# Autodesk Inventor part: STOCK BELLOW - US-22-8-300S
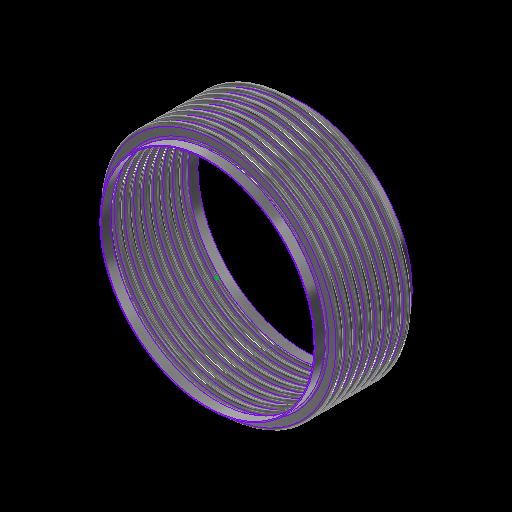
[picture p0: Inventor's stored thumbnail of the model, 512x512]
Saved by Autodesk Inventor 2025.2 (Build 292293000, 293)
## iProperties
Category: 16 GA (0.060 THICK)
RuleStatus: InUse
Created: 2024-01
Part Number: STOCK BELLOW - US-22-8-300S
Project: =STOCK BELLOWS: <Stock Number><SFILL>
Material: ASTM A240-304
Description: =STOCK BELLOWS: <Stock Number>, <SID_> I.D., <SOD_> O.D., <SPLY_> PLY, <Category>, <SNET_CONS> CONS.<PITCH_><STANGENT_> TANGENT<SFILL>
Document SubType Name: Sheet Metal
Designer: GS
Stock Number: U.S-22-8-300S
Surface Area: 25469.6 cm^2
Volume: 3832.38 cm^3
Sheet Metal Rule: Default
Appearance: STAINLESS STEEL
Mass: 30878.6 g
Density: 8.05729 g/cm^3
THK: 0.036
ID: 3.500
OD: 4.250
CONS_: 2
PITCH: 0.500
TANGENT: 0.500
BELLOWS_UPSET: 0.000
d79: 1.000
d82: 1.000
d83: 26.000
d84: 24.000
d174: 8
d214: 8
STHK_: 0.060
SID_: 22.000
SOD_: 24.750
SPITCH_: 1.000
STANGENT__: 1.000
SBELLOWS_UPSET_: 0.000
SDIFF_TAN: 1.000
d252: 2
d275: 2
d287: 0.050
d289: 0.500
d290: 0.000
SOD_NECK: 22 1/4
PLY: 1
PSET: 4.178
PBAR: 1.035
COUNTER: 1.500
NET_TUBE: 3.071
CONS: 2
S_CONS: 0
NET_CONS: 2
ID_M: 88.90 mm
OD_M: 107.95 mm
THK_M: 0.91 mm
ID_U: 3.500 in
OD_U: 4.250 in
THK_U: 0.036 in
TANGENT2: 0.500
TAN_TO_TAN: 1.000 in
d80: 2.571
d81: 10
SID: 2.375
SCONS_: 8
SPITCH: 0.250
STANGENT_: 1.000
SBELLOWS_UPSET: 0.000
SNET_CONS: 8
SS_CONS: 0
SCONS: 8
d190: 8
d191: 1
d192: 1
d193: 8
d194: 0
SIZE: 22.00
PRESSURE: 300
d230: 8
STANGENT: 4.000
SPLY_: 2
d233: 8
d234: 0
d263: 2
d265: 1
d268: 2
d269: 0
d286: 2
d288: 1
d291: 2
d292: 0
SREROLL: 0.750
BLETP: 0.000 ul
PRES_Copy: 85
MATTABLE: 20 GA (0.036 THICK)
PART_NUMBER: U.S-22-8-300S
PITCH_: =, <SPITCH_> PITCH,
CFILL: .
SFILL: .
MESH: ,
COMP: 1.4
EXT: 0.70
LAT: 0.16
ANG: 344
ASR: 9507
LSR: 121742
ANSR: 17434
PRES: 300
COMPM: 14.0
EXTM: 7.0
LATM: 1.60
ASRM: 1664.961
PRESM: 20.684
LSRM: 21320.676
ANSRM: 3053.216
TEMPMIN: 20
TEMPMAX: 800
TEMPMINM: -7
TEMPMAXM: 427
WEIGHTM: 30.879
WEIGHT: 68.076
Author: GS
Keywords: 20 GA (0.036 THICK)
Comments: =STOCK BELLOW - <STOCK NUMBER>
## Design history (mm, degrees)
sketch "Sketch2"
  geometry: L1 (0, -177.245)-(0, 562.856) reference; L2 (45.364, 0)-(44.45, 0); L3 (48.082, -2.718)-(50.343, -2.718); L4 (48.082, -3.632)-(50.343, -3.632); L5 (50.343, -9.982)-(48.082, -9.982); L6 (50.343, -9.068)-(48.082, -9.068); L7 (45.364, -12.7)-(44.45, -12.7); L8 (48.082, 0)-(48.082, -12.7); L9 (50.343, -6.35)-(53.975, -6.35); L10 (44.45, 0)-(44.45, -12.7); L11 (20.376, 102.841)-(20.376, 101.926); L12 (58.262, 457.127)-(58.262, 349.177); L13 (58.262, 444.427)-(58.262, 336.477); L14 (93.133, -58.817)-(93.133, -71.517); L15 (118.746, -66.401)-(118.746, -66.401); L16 (50.343, -9.068)-(50.343, -9.982); L17 (48.082, -9.068)-(48.082, -9.982); L18 (48.082, -9.525)-(50.343, -9.525); L19 (53.975, 0)-(53.975, -12.7); L20 (-50.343, -9.068)-(-50.343, -9.982); L21 (-50.343, -2.718)-(-48.082, -2.718); L22 (-50.343, -3.632)-(-48.082, -3.632); L23 (-48.082, -9.068)-(-50.343, -9.068); L24 (-50.343, -9.525)-(-48.082, -9.525); L25 (-48.082, -9.982)-(-50.343, -9.982); L26 (-48.082, -9.068)-(-48.082, -9.982); L27 (-44.45, 0.653)-(-44.45, -12.047); L28 (-48.082, -6.35)-(-44.45, -6.35); L29 (-50.343, 0.653)-(-50.343, -12.7); L30 (-53.061, 0)-(-53.975, 0); L31 (-53.975, 0)-(-53.975, -12.7); L32 (-53.061, -12.7)-(-53.975, -12.7); A1 r 2.718 centre (48.082, 0) between (45.364, 0) and (48.082, -2.718); A2 r 3.632 centre (48.082, 0) between (44.45, 0) and (48.082, -3.632); A3 r 3.632 centre (50.343, -6.35) between (50.343, -9.982) and (50.343, -2.718); A4 r 2.718 centre (50.343, -6.35) between (50.343, -9.068) and (50.343, -3.632); A5 r 2.718 centre (48.082, -12.7) between (48.082, -9.982) and (45.364, -12.7); A6 r 3.632 centre (48.082, -12.7) between (48.082, -9.068) and (44.45, -12.7); A7 r 3.175 centre (50.343, -6.35) between (50.343, -9.525) and (53.518, -6.35); A8 r 3.175 centre (48.082, -12.7) between (48.082, -9.525) and (44.907, -12.7); A9 r 2.718 centre (-50.343, -12.7) between (-50.343, -9.982) and (-53.061, -12.7); A10 r 2.718 centre (-48.082, -6.35) between (-48.082, -9.068) and (-48.082, -3.632); A11 r 3.175 centre (-48.082, -6.35) between (-48.082, -9.525) and (-44.907, -6.35); A12 r 3.632 centre (-48.082, -6.35) between (-48.082, -9.982) and (-48.082, -2.718); A13 r 3.175 centre (-50.343, -12.7) between (-50.343, -9.525) and (-53.518, -12.7); A14 r 3.632 centre (-50.343, -12.7) between (-50.343, -9.068) and (-53.975, -12.7); A15 r 2.718 centre (-50.343, 0) between (-53.061, 0) and (-50.343, -2.718); A16 r 3.632 centre (-50.343, 0) between (-53.975, 0) and (-50.343, -3.632); 10 further points
  constraints: 62 end point, 38 point on circle, 20 tangent, 16 centre point, 12 parallel, 9 midpoint, 7 vertical, 6 coincident, 6 concentric, 6 point on line, 4 equal radius, 4 perpendicular, 3 horizontal, 1 collinear, 1 horizontal alignment, 10 other
  dimensions: "THK" = 0.9144 distance of L11.start L11.end; "ID" = 88.9 distance of L11.end point (20.376, 13.026); "OD" = 107.95 distance of L12.start L12.end; "PITCH" = 12.7 distance of L12.start L13.start; "TANGENT" = 12.7 distance of L14.start L14.end; "BELLOWS_UPSET" = 0 distance of L15.start L15.end; "d43" = 88.9 diameter of L10 L1 (= ID); "d44" = 107.95 diameter of L9.end L1 (= OD); "d45" = 0.9144 distance between parallel lines of L5 L6 (computed from THK, PLY); "d46" = 3.6322 radius of A3 (computed from PITCH, THK, PLY); "UPSET_PITCH" = 12.7 distance of L2.end L7.end (derived); "SIDEWALL_ANGLE" = 360 deg dimension on L3 L9 (derived); "CON_GAP" = 5.4356 distance of point (48.082, -9.068) point (48.082, -3.632) (derived); "TAN1" = 4.98728 dimension on A8 (derived); "TAN2" = 4.98728 dimension on A7 (derived); "LEG1" = 2.2606 distance of L18.start L18.end (derived); "d278" = 0.9144 distance between parallel lines of L25 L23 (derived); "d279" = 3.6322 radius of A12 (derived); "d280" = 12.7 distance of L30.end L31.end (derived); "d281" = 360 deg dimension on L21 L28 (derived); "d282" = 5.4356 distance of point (-50.343, -9.068) point (-50.343, -3.632) (derived); "d283" = 4.98728 dimension on A13 (derived); "d284" = 4.98728 dimension on A11 (derived); "d285" = 2.2606 distance of L24.start L24.end (derived); "d293" = 88.9 diameter of L27 L1 (derived); "d294" = 107.95 diameter of L31 L1 (derived)
  node "Sketch Rectangular Pattern1" dims "d31" = 25.4, "ID" = 88.9
  node "Sketch Rectangular Pattern2" dims "d39" = 25.4, "PITCH" = 12.7
revolve "CONS" stored, may be unused: angle "d48" = 90 deg
node "BELLOW MIDPLANE"
pattern_linear "Rectangular Pattern2" dims "d52" = 12.7 (= UPSET_PITCH)
sketch "Sketch5"
  geometry: C1 r 45.364 at (0, 0) reference; C2 r 44.45 at (0, 0) reference
extrude "TANGENT" new body sketch "Sketch5" distance "d53" = 12.7 (= TANGENT); taper "d54" = 0 deg
revolve "SAMETAN" stored, may be unused: angle "d65" = 90 deg
revolve "DIFFTAN" stored, may be unused: angle "d70" = 90 deg
sketch "Sketch9"
  geometry: L1 (53.319, 0)-(-53.319, 0) reference; L2 (0, -17.78)-(0, 17.78) reference; L3 (38.085, 0)-(-38.085, 0); L4 (38.085, -11.906)-(38.085, 11.906); L5 (25.385, -11.906)-(25.385, 11.906); L6 (13.15, 11.906)-(13.15, -11.906); L7 (-25.385, -11.906)-(-25.385, 11.906); L8 (-38.085, -11.906)-(-38.085, 11.906); L9 (37.291, -11.906)-(37.291, 11.906); L10 (38.085, -11.906)-(37.291, -11.906); L11 (38.085, 11.906)-(37.291, 11.906); L12 (13.546, 11.906)-(12.753, 11.906); L13 (12.753, 11.906)-(12.753, -11.906); L14 (12.753, -11.906)-(13.546, -11.906); L15 (13.546, -11.906)-(13.546, 11.906); L16 (-13.546, 11.906)-(-13.546, -11.906); L17 (-13.15, 11.906)-(-13.15, -11.906); L18 (-13.546, -11.906)-(-12.753, -11.906); L19 (-12.753, -11.906)-(-12.753, 11.906); L20 (-12.753, 11.906)-(-13.546, 11.906); L21 (-38.085, -11.906)-(-37.291, -11.906); L22 (-37.291, -11.906)-(-37.291, 11.906); L23 (-37.291, 11.906)-(-38.085, 11.906); L24 (-38.085, 11.906)-(-38.085, -11.906); L25 (38.085, -0.397)-(-38.085, -0.397); L26 (-38.085, -0.397)-(-38.085, 0.397); L27 (-38.085, 0.397)-(38.085, 0.397); L28 (38.085, 0.397)-(38.085, -0.397); L29 (-38.085, 11.906)-(38.085, 11.906); L30 (38.085, 11.906)-(38.085, 12.7); L31 (38.085, 12.7)-(-38.085, 12.7); L32 (-38.085, 12.7)-(-38.085, 11.906); L33 (38.085, -11.906)-(-38.085, -11.906); L34 (-38.085, -11.906)-(-38.085, -12.7); L35 (-38.085, -12.7)-(38.085, -12.7); L36 (38.085, -12.7)-(38.085, -11.906); 30 further points
  constraints: 68 end point, 13 midpoint, 13 parallel, 8 horizontal, 7 perpendicular, 6 equal length, 3 point on line, 2 vertical, 14 other
  dimensions: "d115" = 23.8125 distance of L4.start L4.end (derived); "d116" = 12.7 distance between parallel lines of L4 L5 (derived); "d117" = 12.23516 distance between parallel lines of L5 L6 (derived); "d125" = 38.53427 distance between parallel lines of L7 L6 (derived); "d127" = 12.7 distance between parallel lines of L8 L7 (derived); "d128" = 24.93516 distance between parallel lines of L6 L4 (derived); "d130" = 76.16943 distance between parallel lines of L8 L4 (derived); "RULER_THK" = 0.79375 distance between parallel lines of L4 L9; "d135" = 0.79375 distance of L13.end L14.end (derived); "d138" = 26.29911 distance of L13.end L16.end (derived); "d143" = 0.79375 distance of L22.end L8.end (derived); "d144" = 0.79375 distance between parallel lines of L27 L25 (derived)
extrude "RULER" join sketch "Sketch9" distance "d149" = 0.79375 (derived); taper "d150" = 0 deg
extrude "BARS" join sketch "Sketch9" distance "d151" = 0.79375 (derived); taper "d152" = 0 deg
pattern_linear "Rectangular Pattern4" dims "d155" = 26.29911 (derived)
sketch "Sketch13"
  geometry: L1 (93.149, -52.467)-(93.149, -77.867); L2 (282.448, 0)-(279.4, 0); L3 (282.448, -25.4)-(279.4, -25.4); L4 (306.451, -20.574)-(287.274, -20.574); L5 (306.451, -17.526)-(287.274, -17.526); L6 (306.451, -12.7)-(314.325, -12.7); L7 (287.274, -4.826)-(306.451, -4.826); L8 (287.274, 0)-(287.274, -25.4); L9 (279.4, 0)-(279.4, -25.4); L10 (58.254, 132.219)-(58.254, -496.431); L11 (58.254, 106.819)-(58.254, -521.831); L12 (58.254, 56.019)-(58.254, -572.631); L13 (58.254, 30.619)-(58.254, -598.031); L14 (58.254, 5.219)-(58.254, -623.431); L15 (58.254, -20.181)-(58.254, -648.831); L16 (58.254, -45.581)-(58.254, -674.231); L17 (58.254, 81.419)-(58.254, -547.231); L18 (20.376, 103.45)-(20.376, 101.926); L19 (287.274, -7.874)-(306.451, -7.874); L20 (0, -835.521)-(0, 293.509) reference; L21 (-62.865, 0)-(377.19, 0) reference; A1 r 4.826 centre (287.274, 0) between (282.448, 0) and (287.274, -4.826); A2 r 4.826 centre (287.274, -25.4) between (287.274, -20.574) and (282.448, -25.4); A3 r 7.874 centre (287.274, -25.4) between (287.274, -17.526) and (279.4, -25.4); A4 r 4.826 centre (306.451, -12.7) between (306.451, -17.526) and (306.451, -7.874); A5 r 7.874 centre (306.451, -12.7) between (306.451, -20.574) and (306.451, -4.826); A6 r 7.874 centre (287.274, 0) between (279.4, 0) and (287.274, -7.874); 6 further points; 1 other entity
  constraints: 38 end point, 15 point on circle, 9 tangent, 6 centre point, 6 parallel, 5 vertical alignment, 4 point on line, 4 vertical, 3 coincident, 3 concentric, 2 collinear, 2 equal radius, 1 horizontal, 1 perpendicular, 23 other
  dimensions: "SBELLOWS_UPSET_" = 0 distance of point (118.762, -66.401) point (118.762, -66.401); "STOTAL_THK_BELLOW__" = 3.048 distance between parallel lines of L4 L5 (derived); "d224" = 7.874 radius of A5 (derived); "d225" = 25.4 distance of L2.end L3.end (derived); "SSIDEWALL_ANGLE_" = 360 deg dimension on L7 L6 (derived); "SSCON_GAP_" = 9.652 distance of point (287.274, -17.526) point (287.274, -7.874) (derived); "d235" = 558.8 diameter of L9 L20 (derived); "d236" = 628.65 diameter of L6.end L20 (derived)
  node "Sketch Rectangular Pattern4" dims "d228" = 25.4
  node "Sketch Rectangular Pattern5" dims "d229" = 25.4
revolve "SBELLOW" stored, may be unused: angle "d197" = 90 deg
pattern_linear "Rectangular Pattern5" dims "d204" = 25.4 (derived)
revolve "STANGENT" stored, may be unused: angle "d240" = 90 deg
revolve "SSAMETAN" stored, may be unused: angle "d241" = 90 deg
revolve "SDIFFTAN" stored, may be unused: angle "d246" = 90 deg
revolve "INVCON" stored, may be unused: angle "d295" = 90 deg
pattern_linear "Rectangular Pattern6" dims "d298" = 12.7 (derived)
revolve "INVTANGENT" stored, may be unused: angle "d302" = 90 deg
revolve "INVSAMETAN" stored, may be unused: angle "d307" = 90 deg
revolve "INVDIFFTAN" stored, may be unused: angle "d312" = 90 deg
sketch "ID BELLOW MOUNT CALC"
  geometry: L1 (44.45, 0)-(38.1, 0); L2 (38.1, 0)-(38.1, 12.7); L3 (38.1, 12.7)-(44.45, 12.7); L4 (44.45, 12.7)-(44.45, 0); L5 (36.513, 12.7)-(35.598, 12.7); L6 (35.598, 12.7)-(35.598, 0); L7 (35.598, 0)-(36.513, 0); L8 (36.513, 0)-(36.513, 12.7); L9 (0, -2.54)-(0, 15.24) reference; L10 (-8.89, 0)-(53.34, 0) reference; 1 further point
  constraints: 16 end point, 5 parallel, 2 collinear, 2 horizontal, 2 perpendicular
  dimensions: "d314" = 12.7 distance of L5.end L6.end (derived); "d315" = 0.9144 distance of L5.start L5.end (derived); "IG" = 1.5875 distance between parallel lines of L2 L8; "PIPE_OD" = 88.9 diameter of L4 L9; "PIPE_WALL" = 6.35 distance of L2.end L3.end; "ID_MT_BELLOW" = 71.1962 diameter of L6 L9 (derived)
revolve "CFILL" stored, may be unused: angle "d320" = 90 deg
pattern_linear "Rectangular Pattern7" dims "d323" = 12.7 (derived)
revolve "SFILL" stored, may be unused: angle "d324" = 90 deg
pattern_linear "Rectangular Pattern8" dims "d327" = 25.4 (derived)
node "STOCK BELLOW MIDPLANE"
node "BELLOW"
sketch "Sketch6"
  geometry: L1 (-12.7, 45.364)-(0, 45.364); L2 (0, 45.364)-(0, 44.45); L3 (0, 44.45)-(-12.7, 44.45); L4 (-12.7, 44.45)-(-12.7, 45.364); L5 (10.16, 0)-(-60.96, 0) reference; L6 (-38.1, -89.422)-(-38.1, 153.44) reference; 1 further point
  constraints: 8 end point, 2 parallel, 1 horizontal, 1 perpendicular
  dimensions: "d61" = 12.7 distance of L2.end L3.end (derived); "d62" = 0.9144 distance of L1.end L2.end (derived); "d63" = 88.9 diameter of L3 L5 (derived); "d64" = 25.4 distance between parallel lines of L4 L6 (derived)
sketch "Sketch12"
  geometry: 1 further point
sketch "Sketch14"
  geometry: L1 (-25.4, 282.448)-(0, 282.448); L2 (0, 282.448)-(0, 279.4); L3 (0, 279.4)-(-25.4, 279.4); L4 (-25.4, 279.4)-(-25.4, 282.448); L5 (5.08, 0)-(-30.48, 0) reference; L6 (0, -56.49)-(0, 338.938) reference; 1 further point
  constraints: 8 end point, 2 parallel, 1 collinear, 1 horizontal, 1 perpendicular
  dimensions: "d237" = 3.048 distance of L3.end L1.start (derived); "d238" = 558.8 diameter of L3 L5 (derived); "d239" = 25.4 distance of L1.start L1.end (derived); "SOD_NECK" = 564.896 diameter of L1 L5 (derived)
sketch "Sketch15"
  geometry: L1 (-56.49, 0)-(338.938, 0) reference; L2 (279.4, -203.2)-(282.448, -203.2); L3 (282.448, -203.2)-(282.448, -228.6); L4 (282.448, -228.6)-(279.4, -228.6); L5 (279.4, -228.6)-(279.4, -203.2); L6 (0, -276.86)-(0, 60.96) reference; 1 further point
  constraints: 8 end point, 2 parallel, 1 horizontal, 1 perpendicular
  dimensions: "d205" = 25.4 distance of L4.end L2.start (derived); "d206" = 3.048 distance of L3.end L4.end (derived); "d207" = 558.8 diameter of L5 L6 (derived); "d208" = 203.2 distance between parallel lines of L1 L2 (derived)
node "TANGENT_"
node "SAME_TAN"
sketch "Sketch8"
  geometry: L1 (45.364, -25.4)-(44.45, -25.4); L2 (44.45, -25.4)-(44.45, -38.1); L3 (44.45, -38.1)-(45.364, -38.1); L4 (45.364, -38.1)-(45.364, -25.4); L5 (0, -48.26)-(0, 22.86) reference; L6 (-89.422, 0)-(153.44, 0) reference; 1 further point
  constraints: 8 end point, 2 parallel, 1 horizontal, 1 perpendicular
  dimensions: "d66" = 88.9 diameter of L2 L5 (derived); "TOTAL_THK_BELLOW" = 0.9144 distance of L2.end L3.end (derived); "d68" = 25.4 distance between parallel lines of L1 L6 (derived); "d69" = 12.7 distance of L1.end L2.end (derived)
node "DIFF_TAN"
node "Sketch Rectangular Pattern3" dims "d138" = 26.29911 (derived), "d141" = 25.4
node "SBELLOW_"
node "STANGENT_"
node "SSAME_TAN"
sketch "Sketch16"
  geometry: L1 (282.448, -203.2)-(279.4, -203.2); L2 (279.4, -203.2)-(279.4, -228.6); L3 (279.4, -228.6)-(282.448, -228.6); L4 (282.448, -228.6)-(282.448, -203.2); L5 (0, -276.86)-(0, 60.96) reference; L6 (-56.49, 0)-(338.938, 0) reference; 1 further point
  constraints: 8 end point, 2 parallel, 1 horizontal, 1 perpendicular
  dimensions: "SDIFF_TAN" = 25.4 distance of L3.end L1.start; "d243" = 3.048 distance of L2.end L3.end (derived); "d244" = 203.2 distance between parallel lines of L1 L6 (derived); "d245" = 558.8 diameter of L2 L5 (derived)
node "SDIFF_TAN"
body "Solid15"
sketch "Sketch17"
  geometry: L1 (53.975, 12.7)-(53.061, 12.7); L2 (53.061, 12.7)-(53.061, 0); L3 (53.061, 0)-(53.975, 0); L4 (53.975, 0)-(53.975, 12.7); L5 (0, -2.54)-(0, 15.24) reference; L6 (-10.795, 0)-(64.77, 0) reference; 2 further points
  constraints: 8 end point, 2 parallel, 1 horizontal, 1 midpoint, 1 perpendicular, 1 point on line
  dimensions: "INVTANGENT" = 12.7 distance of L3.end L1.start (derived); "d300" = 0.9144 distance of L1.start L1.end (derived); "d301" = 107.95 diameter of L4 L5 (derived)
body "Solid16"
sketch "Sketch18"
  geometry: L1 (53.975, -25.4)-(53.061, -25.4); L2 (53.061, -25.4)-(53.061, -38.1); L3 (53.061, -38.1)-(53.975, -38.1); L4 (53.975, -38.1)-(53.975, -25.4); L5 (-10.795, 0)-(64.77, 0) reference; L6 (0, -48.26)-(0, 22.86) reference; 1 further point
  constraints: 8 end point, 2 parallel, 1 horizontal, 1 perpendicular
  dimensions: "d303" = 25.4 distance between parallel lines of L1 L5 (derived); "d304" = 12.7 distance of L3.end L1.start (derived); "d305" = 0.9144 distance of L2.end L3.end (derived); "d306" = 107.95 diameter of L4 L6 (derived)
body "Solid17"
sketch "Sketch19"
  geometry: L1 (53.975, -25.4)-(53.061, -25.4); L2 (53.061, -25.4)-(53.061, -38.1); L3 (53.061, -38.1)-(53.975, -38.1); L4 (53.975, -38.1)-(53.975, -25.4); L5 (0, -48.26)-(0, 22.86) reference; L6 (-10.795, 0)-(64.77, 0) reference; 1 further point
  constraints: 8 end point, 2 parallel, 1 horizontal, 1 perpendicular
  dimensions: "d308" = 12.7 distance of L1.end L2.end (derived); "d309" = 107.95 diameter of L4 L5 (derived); "d310" = 0.9144 distance of L2.end L3.end (derived); "d311" = 25.4 distance between parallel lines of L1 L6 (derived)
body "Solid18"
body "Solid19"
body "Solid20"
other parameters: "BMPL" = -101.6, "PSET" = 106.1212 (computed from OD, THK, PLY) [user parameter], "PBAR" = 26.29911 (= 0.570796 x PITCH + OD - ID) [user parameter; used in 1 equation term], "COUNTER" = 15 [user parameter], "NET_TUBE" = 77.99823 (computed from CONS_, PBAR, TANGENT) [user parameter], "S_CONS" = 0 [user parameter; used in 1 equation term], "ID_M" = 88.9 (= ID) [user parameter], "OD_M" = 107.95 (= OD) [user parameter], "THK_M" = 0.9144 (= THK) [user parameter], "ID_U" = 88.9 (= ID) [user parameter], "OD_U" = 107.95 (= OD) [user parameter], "THK_U" = 0.9144 (= THK) [user parameter], "D_UNITS" = 0 [user parameter], "TANGENT2" = 12.7 [user parameter], "TAN_TO_TAN" = 25.4 [user parameter], "OD_NECK" = 90.7288 [user parameter], "d79" = 25.4, "d80" = 65.29823 [user parameter], "d82" = 25.4, "d83" = 660.4, "d84" = 609.6, "sa_0" = 4, "FRAME_THK" = 0.79375 [user parameter], "CON_FLAT" = 12.23516 [user parameter], "SID" = 60.325 [user parameter], "SPITCH" = 6.35 [user parameter], "STANGENT_" = 25.4 [user parameter], "SBELLOWS_UPSET" = 0 [user parameter], "SS_CONS" = 0 [user parameter], "STAN_TO_TAN_" = 203.2 [user parameter], "d100" = 3.048 [user parameter], "d191" = 25.4 [user parameter], "d194" = 0 [user parameter], "STANGENT" = 101.6 [user parameter], "d234" = 0 [user parameter], "SUPSET_PITCH_" = 25.4 [user parameter], "d269" = 0 [user parameter], "d287" = 1.27, "d289" = 12.7, "d290" = 0, "d292" = 0 [user parameter], "Thickness" = 3.048 (derived), "KFactor" = 4.4, "BendRadius" = 3.048 (derived), "BendReliefWidth" = 3.048 (derived), "BendReliefDepth" = 1.524 (derived), "CornerReliefSize" = 12.192 (derived), "SeamGap" = 0.00508, "MinimumRemnant" = 6.096 (derived), "TransitionRadius" = 3.048 (derived), "JacobiRadiusSize" = 3.048 (derived), "GapSize" = 3.048 (derived), "SREROLL" = 19.05 [user parameter], "CUR_STK_PITCH" = 25.4 [user parameter], "d328" = -101.6 (derived), "ASR" = 95070 [user parameter], "LSR" = 1217420 [user parameter], "ANSR" = 174340 [user parameter], "BLETP" = 0 [user parameter], "ASRM" = 16649.6091 [user parameter], "PRESM" = 206.83949 [user parameter], "LSRM" = 213206.7646 [user parameter], "ANSRM" = 30532.1642 [user parameter], "TEMPMIN" = 2664.83333 [user parameter], "TEMPMAX" = 6998.16667 [user parameter], "TEMPMINM" = 2664.83333 [user parameter], "TEMPMAXM" = 6998.16667 [user parameter], "WEIGHT" = 308.78566 [user parameter], "WEIGHTM" = 0.30879 [user parameter]
